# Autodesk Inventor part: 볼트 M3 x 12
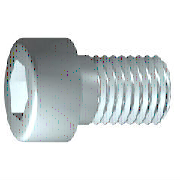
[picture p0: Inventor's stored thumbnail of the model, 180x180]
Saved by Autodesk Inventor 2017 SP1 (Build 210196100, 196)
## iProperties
IsCustomPart: 0
Created: 2012-02
Part Number: 볼트 M3 x 12
Material: 강철, 연강
Description: 6각머리 태핑 나사
Document SubType Name: Modeling
Standard: KS B 1003
Designer: mduedu
Standards Organization: KS
Language: ko-KR
Size Designation: M 3 x 12
Categories: <MemberInstance><Categories><Category DisplayName="조임쇠" InternalName="e4da775c-781d-43d5-af7c-5136215cf5a6" Mnemonic="FSTN"><Category DisplayName="볼트" InternalN
Density: 7.86 g/cm^3
Mass: 1.20764 g
Surface Area: 2.30125 cm^2
Volume: 0.153644 cm^3
Appearance: 강철
Author: mduedu
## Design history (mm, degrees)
sketch "스케치1"
  geometry: L1 (-0.867, 0)-(13, 0); L2 (13, 0)-(13, 1.5); L3 (13, 1.5)-(1.25, 1.5); L4 (1.25, 1.5)-(0.943, 1.5); L5 (0.943, 1.5)-(0, 1.5); L6 (0, 1.5)-(0, 2.75); L7 (0, 2.75)-(-3, 2.75); L8 (-3, 2.75)-(-3, 1.443); L9 (-3, 1.443)-(-1.7, 1.443); L10 (-1.7, 1.443)-(-0.867, 0); L11 (-6.2, 0)-(16.2, 0) reference; L12 (0, -0.55)-(0, 3.3) reference; L13 (1.25, 1.5)-(0, 1.5)
  constraints: 22 end point, 6 parallel, 2 collinear, 2 perpendicular, 1 horizontal, 1 point on line
  dimensions: "d1" = 11.75 distance from line of L3.end L2 (= GEL); "d2" = 0.30683 distance of L4.end L3.end (computed from GAL); "d3" = 3 distance between parallel lines of L8 L6 (= KOH); "d4" = 1.3 distance of L8.end L9.end (= INTI); "d5" = 60 deg angle of L10 L1; "d6" = 3 diameter of L3 L1 (= GD); "d7" = 3 diameter of L5 L1 (= BDM); "d8" = 2.88675 diameter of L9 L1 (= 1.1547 x SW); "d9" = 5.5 diameter of L7 L1 (= KOD); "d26" = 13 distance between parallel lines of L12 L2 (= NLG)
revolve "본체" sketch "스케치1" stored, may be unused: angle "d10" = 90 deg
sketch "스케치2"
  geometry: L1 (0, -3.85)-(0, 3.85) reference; L2 (-3.85, 0)-(3.85, 0) reference; L3 (1.443, 0)-(0.722, -1.25); L4 (0.722, -1.25)-(-0.722, -1.25); L5 (-0.722, -1.25)-(-1.443, 0); L6 (-1.443, 0)-(-0.722, 1.25); L7 (-0.722, 1.25)-(0.722, 1.25); L8 (0.722, 1.25)-(1.443, 0); 2 further points
  constraints: 12 end point, 1 coincident, 1 horizontal alignment, 1 point on line, 12 other
extrude "슬롯" join sketch "스케치2" stored distance "d11" = 10; taper "d12" = 0 deg
workplane "Work Plane1"
fillet "Fillet2" dims "d30" = 0.1 (= R)
body "Solid1"
fillet "모깎기1" dims "d17" = 0.3 (= RR)
feature "스레드" dims "d13" = 11.75 (= GEL), "d14" = 0
chamfer "모따기1" distance "d15" = 0.30673 (= -0.5 x SPD + 0.5 x GD); stored, may be unused: second distance "d16" = 0.30673 (= GUL), angle "d27" = 45 deg
other parameters: "GD" = 3 (= NND) [user parameter; used in 2 equation terms], "NLG" = 13 [user parameter; used in 1 equation term], "GEL" = 11.75 [user parameter; used in 2 equation terms], "KOD" = 5.5 [user parameter; used in 1 equation term], "KOH" = 3 [user parameter; used in 1 equation term], "INTI" = 1.3 [user parameter; used in 1 equation term], "GAL" = 0.30673 (= 0.61345 x PTC) [user parameter; used in 1 equation term], "GUL" = 0.30673 (= 0.61345 x PTC) [user parameter; used in 1 equation term], "BDM" = 3 (= NND) [user parameter; used in 1 equation term], "SW" = 2.5 [user parameter; used in 2 equation terms], "RR" = 0.3 [user parameter; used in 1 equation term], "SPD" = 2.38655 (= NND - 1.2269 x PTC) [user parameter; used in 1 equation term], "d19" = 0, "d28" = 0, "d29" = 0, "R" = 0.1 [user parameter; used in 1 equation term], "PHH" = 0.1 [user parameter], "GD1" = 2.38655 (= THREADDIA - 1.2269 x PTC) [user parameter], "THREADDIA" = 3 [user parameter; used in 1 equation term], "FAWI" = 45 deg [user parameter], "PTC" = 0.5 [user parameter; used in 5 equation terms], "NND" = 3 [user parameter; used in 3 equation terms], "TOA" = 30 deg [user parameter], "E0" = 2.8875 (= 1.155 x SW) [user parameter]
